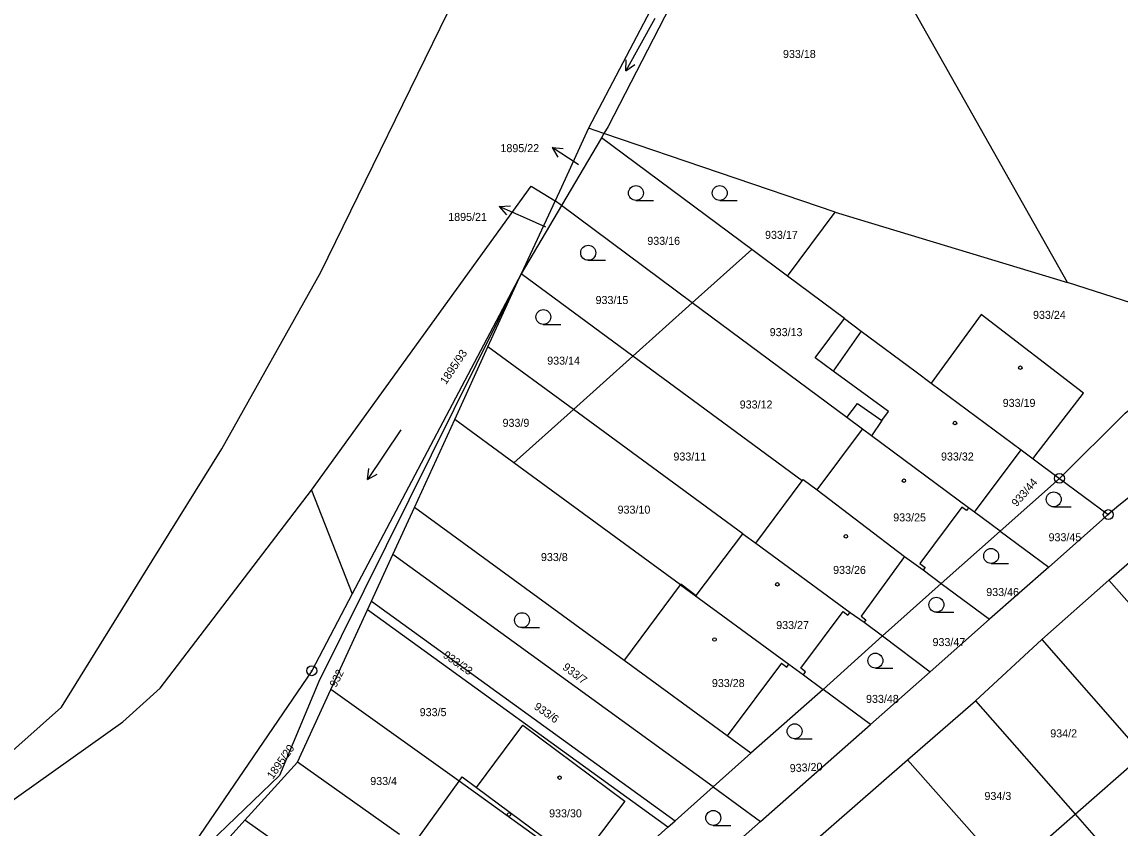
# Model space of a CAD drawing. Extents: x -587171 to -555306, y -1167727 to -1074732.
# Drawn here: x -560264.8 to -560154.7, y -1077465.8 to -1077384.9 of the extents above; entities that cross this region are included whole.
import ezdxf

# ---------------------------------------------------------------- set-up
doc = ezdxf.new("R2010")
doc.units = 0
for name, color, linetype in [('Hranice parcel', 7, 'Continuous'), ('Parcelní čísla', 7, 'Continuous'), ('Pop  PČ popisy', 7, 'Continuous'), ('Vnitřní kresba', 7, 'Continuous'), ('Značky bodu BP', 7, 'Continuous'), ('Značky budov', 7, 'Continuous'), ('Značky kultur', 7, 'Continuous')]:
    doc.layers.add(name, color=color, linetype=linetype)

msp = doc.modelspace()

# ---------------------------------------------------------------- linework, layer by layer
at = {"layer": 'Hranice parcel'}
for p, q in [((-560188.63, -1077358.57), (-560207.98, -1077395.56)), ((-560159.94, -1077411.03), (-560185.9, -1077365.07)), ((-560234.84, -1077410), (-560220.81, -1077381.27)), ((-560206.44, -1077396.09), (-560207.98, -1077395.56)), ((-560206.69, -1077396.52), (-560210.7, -1077403.3)), ((-560206.44, -1077396.09), (-560206.69, -1077396.52)), ((-560191.62, -1077407.73), (-560206.69, -1077396.52)), ((-560183.26, -1077403.97), (-560206.44, -1077396.09)), ((-560211.33, -1077402.83), (-560214.76, -1077410.16)), ((-560210.7, -1077403.3), (-560214.76, -1077410.16)), ((-560210.7, -1077403.3), (-560211.33, -1077402.83)), ((-560197.58, -1077413.08), (-560210.7, -1077403.3)), ((-560188.04, -1077410.39), (-560183.26, -1077403.97)), ((-560183.26, -1077403.97), (-560159.94, -1077411.03)), ((-560191.62, -1077407.73), (-560197.58, -1077413.08)), ((-560188.04, -1077410.39), (-560191.62, -1077407.73)), ((-560244.78, -1077427.73), (-560234.84, -1077410)), ((-560214.76, -1077410.16), (-560231.69, -1077442.28)), ((-560218.09, -1077417.49), (-560214.76, -1077410.16)), ((-560203.54, -1077418.43), (-560214.76, -1077410.16)), ((-560182.3, -1077414.66), (-560188.04, -1077410.39)), ((-560197.58, -1077413.08), (-560203.54, -1077418.43)), ((-560182.06, -1077424.6), (-560197.58, -1077413.08)), ((-560221.39, -1077424.78), (-560218.09, -1077417.49)), ((-560209.51, -1077423.77), (-560218.09, -1077417.49)), ((-560203.54, -1077418.43), (-560209.51, -1077423.77)), ((-560186.56, -1077430.94), (-560203.54, -1077418.43)), ((-560173.61, -1077421.13), (-560164.6, -1077427.83)), ((-560215.47, -1077429.12), (-560209.51, -1077423.77)), ((-560192.52, -1077436.25), (-560209.51, -1077423.77)), ((-560225.45, -1077433.63), (-560221.39, -1077424.78)), ((-560215.47, -1077429.12), (-560221.39, -1077424.78)), ((-560180.49, -1077425.76), (-560182.06, -1077424.6)), ((-560185.04, -1077431.84), (-560180.49, -1077425.76)), ((-560251.75, -1077438.96), (-560244.78, -1077427.73)), ((-560169.26, -1077434.09), (-560164.6, -1077427.83)), ((-560164.6, -1077427.83), (-560163.4, -1077428.72)), ((-560198.77, -1077441.37), (-560215.47, -1077429.12)), ((-560163.4, -1077428.72), (-560160.75, -1077430.69)), ((-560166.7, -1077435.99), (-560160.75, -1077430.69)), ((-560160.75, -1077430.69), (-560155.85, -1077434.33)), ((-560235.79, -1077431.89), (-560231.69, -1077442.28)), ((-560191.21, -1077437.19), (-560186.56, -1077430.94)), ((-560227.6, -1077438.32), (-560225.45, -1077433.63)), ((-560204.41, -1077448.98), (-560225.45, -1077433.63)), ((-560166.7, -1077435.99), (-560169.26, -1077434.09)), ((-560155.85, -1077434.33), (-560161.83, -1077439.6)), ((-560155.8, -1077440.89), (-560149.03, -1077435.03)), ((-560192.52, -1077436.25), (-560191.21, -1077437.19)), ((-560172.6, -1077441.23), (-560166.7, -1077435.99)), ((-560166.7, -1077435.99), (-560161.83, -1077439.6)), ((-560229.75, -1077443), (-560227.6, -1077438.32)), ((-560195.5, -1077461.65), (-560227.6, -1077438.32)), ((-560260.86, -1077453.64), (-560251.75, -1077438.96)), ((-560161.83, -1077439.6), (-560167.75, -1077444.83)), ((-560178.51, -1077446.5), (-560172.6, -1077441.23)), ((-560172.6, -1077441.23), (-560167.75, -1077444.83)), ((-560162.51, -1077446.85), (-560155.8, -1077440.89)), ((-560145.61, -1077452.45), (-560155.8, -1077440.89)), ((-560230.15, -1077443.87), (-560229.75, -1077443)), ((-560229.75, -1077443), (-560199.31, -1077465.04)), ((-560233.82, -1077451.86), (-560230.15, -1077443.87)), ((-560200.02, -1077465.68), (-560230.15, -1077443.87)), ((-560167.75, -1077444.83), (-560173.73, -1077450.11)), ((-560184.46, -1077451.86), (-560178.51, -1077446.5)), ((-560178.51, -1077446.5), (-560173.73, -1077450.11)), ((-560169.18, -1077453.02), (-560162.51, -1077446.85)), ((-560162.51, -1077446.85), (-560152.39, -1077458.44)), ((-560173.73, -1077450.11), (-560179.7, -1077455.38)), ((-560237.17, -1077459.16), (-560233.82, -1077451.86)), ((-560220.97, -1077461.08), (-560233.82, -1077451.86)), ((-560184.46, -1077451.86), (-560191.69, -1077458.26)), ((-560179.7, -1077455.38), (-560184.46, -1077451.86)), ((-560273.13, -1077464.57), (-560260.86, -1077453.64)), ((-560175.99, -1077458.92), (-560169.18, -1077453.02)), ((-560169.18, -1077453.02), (-560159.18, -1077464.39)), ((-560190.74, -1077465.12), (-560179.7, -1077455.38)), ((-560195.5, -1077461.65), (-560191.69, -1077458.26)), ((-560242.45, -1077464.98), (-560237.17, -1077459.16)), ((-560226.94, -1077466.44), (-560237.17, -1077459.16)), ((-560186.28, -1077467.93), (-560175.99, -1077458.92)), ((-560175.99, -1077458.92), (-560168.22, -1077467.71)), ((-560159.18, -1077464.39), (-560152.39, -1077458.44)), ((-560225.28, -1077467.06), (-560220.97, -1077461.08)), ((-560210.38, -1077468.68), (-560220.97, -1077461.08)), ((-560219.22, -1077461.72), (-560210.18, -1077468.42)), ((-560199.31, -1077465.04), (-560195.5, -1077461.65)), ((-560195.5, -1077461.65), (-560190.74, -1077465.12)), ((-560247.74, -1077470.8), (-560242.45, -1077464.98)), ((-560218.38, -1077482.04), (-560242.45, -1077464.98)), ((-560206.5, -1077471.46), (-560200.02, -1077465.68)), ((-560200.02, -1077465.68), (-560199.31, -1077465.04))]:
    msp.add_line(p, q, dxfattribs=at)
for points in [[(-560187.93, -1077360.23), (-560206.02, -1077395.38), (-560206.44, -1077396.09)], [(-560207.98, -1077395.56), (-560210.71, -1077401.49), (-560211.33, -1077402.83)], [(-560235.79, -1077431.89), (-560213.75, -1077401.38), (-560211.33, -1077402.83)], [(-560214.76, -1077410.16), (-560235.05, -1077451.08), (-560238.97, -1077460.52), (-560250.37, -1077471.48)], [(-560146.85, -1077415.24), (-560154.41, -1077412.81), (-560159.94, -1077411.03)], [(-560163.4, -1077428.72), (-560163.21, -1077428.46), (-560158.34, -1077422.14), (-560168.6, -1077414.25), (-560173.34, -1077420.76), (-560173.61, -1077421.13)], [(-560182.06, -1077424.6), (-560180.99, -1077423.19), (-560178.55, -1077424.9), (-560177.9, -1077423.98), (-560183.45, -1077419.92), (-560185.24, -1077418.61), (-560182.3, -1077414.66)], [(-560182.3, -1077414.66), (-560180.63, -1077415.91), (-560175.11, -1077420.01), (-560173.61, -1077421.13)], [(-560160.75, -1077430.69), (-560154.16, -1077424.16), (-560144.32, -1077416.06)], [(-560169.26, -1077434.09), (-560169.86, -1077433.64), (-560179.61, -1077426.41), (-560180.49, -1077425.76)], [(-560142.56, -1077426.34), (-560148.97, -1077428.76), (-560154.79, -1077433.4), (-560155.85, -1077434.33)], [(-560186.56, -1077430.94), (-560186.44, -1077430.79), (-560185.04, -1077431.84)], [(-560344.11, -1077542.98), (-560322.5, -1077519.89), (-560300.89, -1077495.53), (-560278.85, -1077472.29), (-560254.7, -1077455.13), (-560250.95, -1077451.74), (-560235.79, -1077431.89)], [(-560185.04, -1077431.84), (-560176.28, -1077438.52), (-560174.41, -1077439.88), (-560172.6, -1077441.23)], [(-560198.77, -1077441.37), (-560198.72, -1077441.29), (-560197.18, -1077442.43), (-560192.52, -1077436.25)], [(-560191.21, -1077437.19), (-560181.73, -1077444.14), (-560180.35, -1077445.11), (-560178.51, -1077446.5)], [(-560204.41, -1077448.98), (-560204.34, -1077448.89), (-560198.77, -1077441.37)], [(-560198.77, -1077441.37), (-560187.9, -1077449.34), (-560186.43, -1077450.4), (-560184.46, -1077451.86)], [(-560231.69, -1077442.28), (-560235.75, -1077449.99), (-560250.37, -1077471.48)], [(-560191.69, -1077458.26), (-560194.09, -1077456.51), (-560204.41, -1077448.98)], [(-560219.22, -1077461.72), (-560214.58, -1077455.47), (-560204.35, -1077463.08), (-560209.01, -1077469.29), (-560210.18, -1077468.42)], [(-560220.97, -1077461.08), (-560220.67, -1077460.65), (-560219.22, -1077461.72)], [(-560165.93, -1077470.29), (-560165.62, -1077470.03), (-560163.3, -1077467.99), (-560159.18, -1077464.39)], [(-560159.18, -1077464.39), (-560150.76, -1077474.02), (-560150.14, -1077474.73)], [(-560190.74, -1077465.12), (-560199.94, -1077473.24), (-560201.76, -1077474.87)]]:
    msp.add_lwpolyline(points, dxfattribs=at)
at = {"layer": 'Pop  PČ popisy'}
for p, q in [((-560209.13, -1077399.12), (-560211.65, -1077397.49)), ((-560211.65, -1077397.49), (-560210.53, -1077397.61)), ((-560211.65, -1077397.49), (-560211.08, -1077398.45)), ((-560208.99, -1077399.22), (-560209.13, -1077399.12)), ((-560216.94, -1077403.4), (-560215.82, -1077403.35)), ((-560214.2, -1077404.62), (-560216.94, -1077403.4)), ((-560216.94, -1077403.4), (-560216.23, -1077404.26)), ((-560212.27, -1077405.48), (-560214.2, -1077404.62))]:
    msp.add_line(p, q, dxfattribs=at)
at = {"layer": 'Vnitřní kresba'}
for p, q in [((-560180.63, -1077415.91), (-560183.45, -1077419.92)), ((-560178.55, -1077424.9), (-560179.61, -1077426.41)), ((-560170.55, -1077433.57), (-560174.76, -1077439.25)), ((-560170.07, -1077433.92), (-560170.55, -1077433.57)), ((-560169.86, -1077433.64), (-560170.07, -1077433.92)), ((-560176.28, -1077438.52), (-560180.65, -1077444.52)), ((-560174.76, -1077439.25), (-560174.23, -1077439.64)), ((-560174.23, -1077439.64), (-560174.41, -1077439.88)), ((-560186.7, -1077449.73), (-560182.45, -1077444.06)), ((-560182.45, -1077444.06), (-560181.96, -1077444.43)), ((-560181.96, -1077444.43), (-560181.73, -1077444.14)), ((-560180.65, -1077444.52), (-560180.17, -1077444.87)), ((-560180.17, -1077444.87), (-560180.35, -1077445.11)), ((-560188.62, -1077449.22), (-560194.09, -1077456.51)), ((-560188.62, -1077449.22), (-560188.1, -1077449.62)), ((-560188.1, -1077449.62), (-560187.9, -1077449.34)), ((-560186.21, -1077450.1), (-560186.7, -1077449.73)), ((-560186.43, -1077450.4), (-560186.21, -1077450.1))]:
    msp.add_line(p, q, dxfattribs=at)
at = {"layer": 'Značky bodu BP'}
for centre, radius in [((-560160.75, -1077430.69), 0.5), ((-560160.75, -1077430.69), 0.0303), ((-560155.85, -1077434.33), 0.5), ((-560155.85, -1077434.33), 0.0303), ((-560235.75, -1077449.99), 0.5), ((-560235.75, -1077449.99), 0.0303)]:
    msp.add_circle(centre, radius, dxfattribs=at)
at = {"layer": 'Značky budov'}
for centre in [(-560164.67, -1077419.59), (-560171.22, -1077425.14), (-560176.35, -1077430.93), (-560182.18, -1077436.51), (-560189.04, -1077441.33), (-560195.35, -1077446.86), (-560210.89, -1077460.72), (-560215.96, -1077464.42)]:
    msp.add_circle(centre, 0.175, dxfattribs=at)
at = {"layer": 'Značky kultur'}
for p, q in [((-560201.34, -1077384.55), (-560204.25, -1077389.79)), ((-560204.25, -1077389.79), (-560204.21, -1077388.7)), ((-560204.25, -1077389.79), (-560203.34, -1077389.18)), ((-560203.23, -1077402.81), (-560201.48, -1077402.81)), ((-560194.83, -1077402.81), (-560193.08, -1077402.81)), ((-560208.02, -1077408.81), (-560206.27, -1077408.81)), ((-560212.52, -1077415.25), (-560210.77, -1077415.25)), ((-560226.8, -1077425.81), (-560230.15, -1077430.79)), ((-560230.15, -1077430.79), (-560230.02, -1077429.7)), ((-560230.15, -1077430.79), (-560229.19, -1077430.26)), ((-560161.32, -1077433.55), (-560159.57, -1077433.55)), ((-560167.6, -1077439.23), (-560165.85, -1077439.23)), ((-560173.09, -1077444.12), (-560171.34, -1077444.12)), ((-560214.66, -1077445.67), (-560212.91, -1077445.67)), ((-560179.21, -1077449.73), (-560177.46, -1077449.73)), ((-560187.31, -1077456.82), (-560185.56, -1077456.82)), ((-560195.47, -1077465.51), (-560193.72, -1077465.51))]:
    msp.add_line(p, q, dxfattribs=at)
for centre in [(-560203.23, -1077402.06), (-560194.83, -1077402.06), (-560208.02, -1077408.06), (-560212.52, -1077414.5), (-560161.32, -1077432.8), (-560167.6, -1077438.48), (-560173.09, -1077443.37), (-560214.66, -1077444.92), (-560179.21, -1077448.98), (-560187.31, -1077456.07), (-560195.47, -1077464.76)]:
    msp.add_circle(centre, 0.75, dxfattribs=at)

# ---------------------------------------------------------------- texts
at = {"layer": 'Parcelní čísla'}
for s, p in [('933/18', (-560188.48, -1077388.51)), ('1895/22', (-560216.82, -1077397.96)), ('1895/21', (-560222.06, -1077404.86)), ('933/16', (-560202.09, -1077407.26)), ('933/17', (-560190.28, -1077406.66)), ('933/15', (-560207.28, -1077413.2)), ('933/24', (-560163.4, -1077414.69)), ('933/13', (-560189.81, -1077416.42)), ('933/14', (-560212.13, -1077419.28)), ('933/12', (-560192.82, -1077423.68)), ('933/19', (-560166.44, -1077423.52)), ('933/9', (-560216.61, -1077425.52)), ('933/11', (-560199.47, -1077428.9)), ('933/32', (-560172.63, -1077428.9)), ('933/10', (-560205.07, -1077434.23)), ('933/25', (-560177.42, -1077435.01)), ('933/45', (-560161.84, -1077437)), ('933/8', (-560212.76, -1077438.99)), ('933/26', (-560183.45, -1077440.28)), ('933/46', (-560168.09, -1077442.5)), ('933/27', (-560189.16, -1077445.81)), ('933/47', (-560173.48, -1077447.52)), ('933/28', (-560195.61, -1077451.63)), ('933/48', (-560180.15, -1077453.22)), ('933/5', (-560224.92, -1077454.55)), ('934/2', (-560161.67, -1077456.68)), ('933/4', (-560229.88, -1077461.46)), ('934/3', (-560168.27, -1077462.96)), ('933/30', (-560211.94, -1077464.7))]:
    msp.add_text(s, height=0.803, dxfattribs=at).set_placement(p)
for s, rotation, p in [('1895/93', 56, (-560222.28, -1077421.33)), ('933/44', 49, (-560165.04, -1077433.6)), ('933/23', 325, (-560222.66, -1077448.59)), ('933/7', 323, (-560210.66, -1077449.78)), ('932', 63, (-560233.31, -1077451.73)), ('933/6', 325, (-560213.53, -1077453.76)), ('1895/20', 55, (-560239.66, -1077460.94)), ('933/20', 3, (-560187.78, -1077460.18))]:
    msp.add_text(s, height=0.803, rotation=rotation, dxfattribs=at).set_placement(p)

doc.saveas('drawing.dxf')
